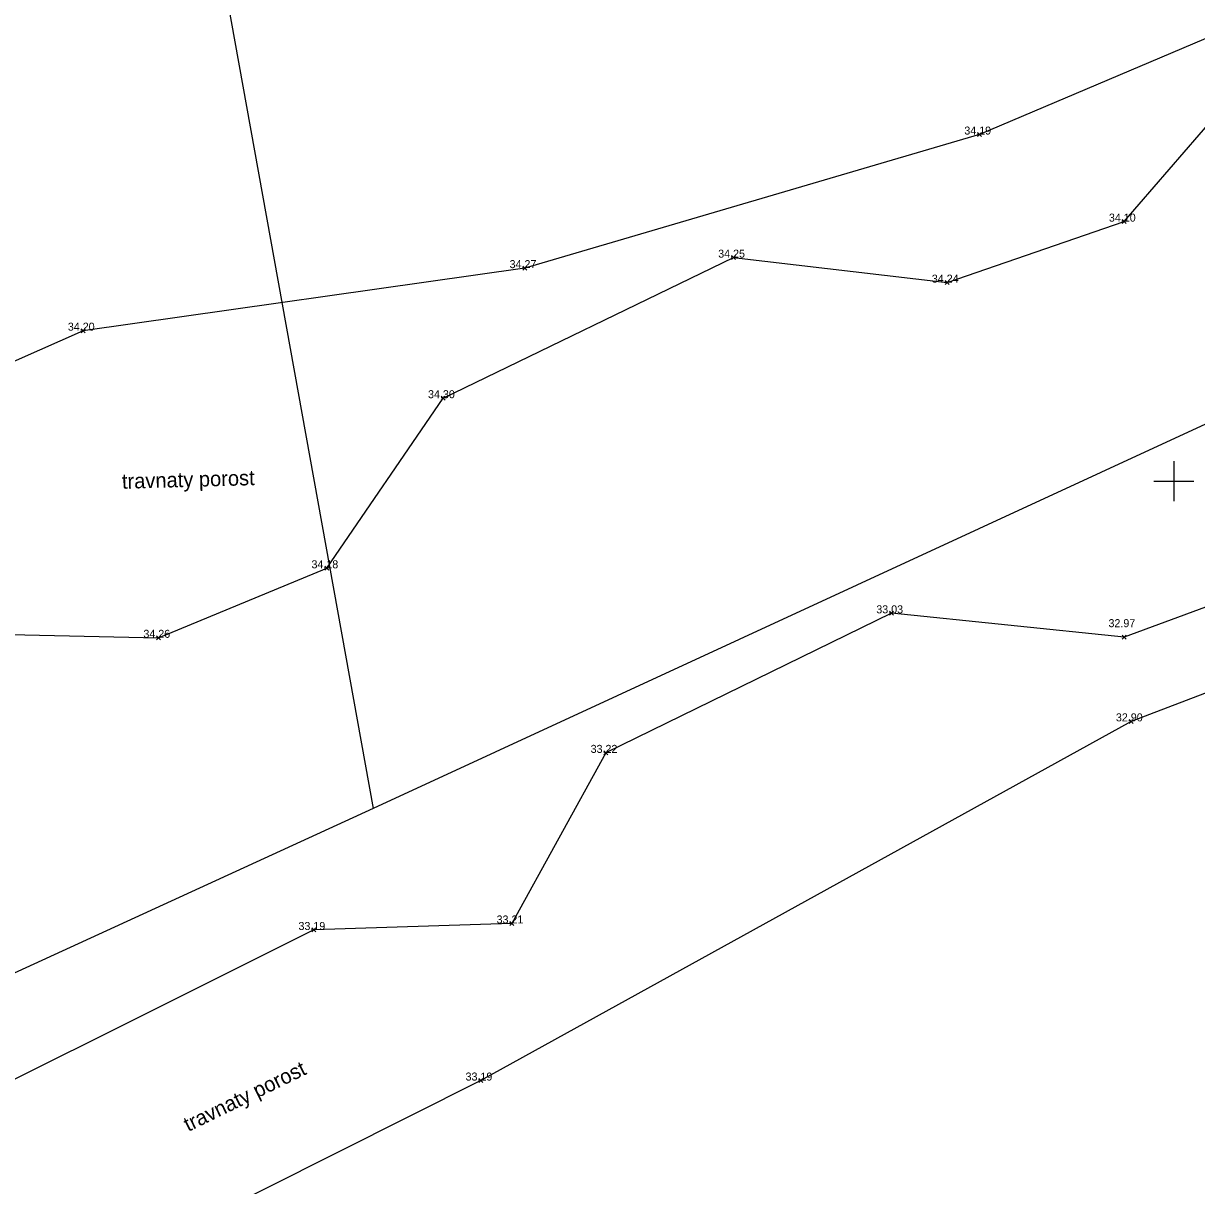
# Model space of a CAD drawing. Extents: x -772865 to -772533, y -1034366 to -1034132.
# Drawn here: x -772747.99 to -772724.54, y -1034264.08 to -1034240.85 of the extents above; entities that cross this region are included whole.
import ezdxf

# ---------------------------------------------------------------- set-up
doc = ezdxf.new("R2010")
doc.units = 0
for name, color, linetype in [('body', 7, 'Continuous'), ('KM_hranice', 7, 'Continuous'), ('mistni_popis', 7, 'Continuous'), ('oddeleni_ploch', 7, 'Continuous'), ('souradnicova_sit', 7, 'Continuous'), ('stromy_kere', 7, 'Continuous'), ('vyskove_koty', 7, 'Continuous')]:
    doc.layers.add(name, color=color, linetype=linetype)

msp = doc.modelspace()

# ---------------------------------------------------------------- linework, layer by layer
at = {"layer": 'body'}
for p, q in [((-772728.84, -1034243.11), (-772728.92, -1034243.03)), ((-772728.92, -1034243.11), (-772728.84, -1034243.03)), ((-772725.95, -1034244.85), (-772726.03, -1034244.77)), ((-772726.03, -1034244.85), (-772725.95, -1034244.77)), ((-772733.76, -1034245.57), (-772733.84, -1034245.49)), ((-772733.84, -1034245.57), (-772733.76, -1034245.49)), ((-772737.93, -1034245.78), (-772738.01, -1034245.7)), ((-772738.01, -1034245.78), (-772737.93, -1034245.7)), ((-772729.49, -1034246.07), (-772729.57, -1034245.99)), ((-772729.57, -1034246.07), (-772729.49, -1034245.99)), ((-772746.76, -1034247.03), (-772746.84, -1034246.95)), ((-772746.84, -1034247.03), (-772746.76, -1034246.95)), ((-772739.56, -1034248.38), (-772739.64, -1034248.3)), ((-772739.64, -1034248.38), (-772739.56, -1034248.3)), ((-772741.89, -1034251.78), (-772741.97, -1034251.7)), ((-772741.97, -1034251.78), (-772741.89, -1034251.7)), ((-772730.6, -1034252.68), (-772730.68, -1034252.6)), ((-772730.68, -1034252.68), (-772730.6, -1034252.6)), ((-772745.25, -1034253.17), (-772745.33, -1034253.09)), ((-772745.33, -1034253.17), (-772745.25, -1034253.09)), ((-772725.95, -1034253.16), (-772726.03, -1034253.08)), ((-772726.03, -1034253.16), (-772725.95, -1034253.08)), ((-772725.81, -1034254.84), (-772725.89, -1034254.76)), ((-772725.89, -1034254.84), (-772725.81, -1034254.76)), ((-772736.31, -1034255.47), (-772736.39, -1034255.39)), ((-772736.39, -1034255.47), (-772736.31, -1034255.39)), ((-772738.19, -1034258.88), (-772738.27, -1034258.8)), ((-772738.27, -1034258.88), (-772738.19, -1034258.8)), ((-772742.15, -1034259.01), (-772742.23, -1034258.93)), ((-772742.23, -1034259.01), (-772742.15, -1034258.93)), ((-772738.81, -1034262.02), (-772738.89, -1034261.94)), ((-772738.89, -1034262.02), (-772738.81, -1034261.94))]:
    msp.add_line(p, q, dxfattribs=at)
at = {"layer": 'KM_hranice'}
for p, q in [((-772747.65, -1034219.69), (-772741, -1034256.54)), ((-772692.32, -1034234.06), (-772741, -1034256.54)), ((-772741, -1034256.54), (-772755.58, -1034263.23))]:
    msp.add_line(p, q, dxfattribs=at)
at = {"layer": 'oddeleni_ploch'}
for points in [[(-772574.1, -1034196.14), (-772586.87, -1034201.34), (-772598.23, -1034205.06), (-772614.53, -1034207.42), (-772626.93, -1034206.95), (-772636.66, -1034207.26), (-772647.96, -1034208.36), (-772659.39, -1034213.08), (-772672.58, -1034218.62), (-772687.49, -1034225.14), (-772703.01, -1034232.02), (-772714.35, -1034236.9), (-772728.88, -1034243.07), (-772737.97, -1034245.74), (-772746.8, -1034246.99), (-772753.85, -1034250.11), (-772762.71, -1034257.3), (-772782.05, -1034269.18), (-772797.09, -1034276.39), (-772810.61, -1034282.39), (-772816.13, -1034284.08), (-772822.76, -1034283.4), (-772826.73, -1034280.27)], [(-772569.67, -1034207.72), (-772578.35, -1034211.18), (-772588.33, -1034216.15), (-772592.11, -1034217.46), (-772598.89, -1034219.1), (-772610.21, -1034219.57), (-772621.14, -1034219.48), (-772637.34, -1034221.06), (-772647.54, -1034222.08), (-772674.34, -1034233.24), (-772685.01, -1034239.21), (-772697.33, -1034242.95), (-772712.12, -1034249.56), (-772725.85, -1034254.8), (-772738.85, -1034261.98), (-772750.37, -1034267.76), (-772764, -1034272.65), (-772783.9, -1034280.59), (-772796.38, -1034286.28), (-772810.31, -1034291.67), (-772823.61, -1034294.35), (-772828.52, -1034296.12), (-772827.01, -1034302.81), (-772823.23, -1034300.75)]]:
    msp.add_lwpolyline(points, dxfattribs=at)
at = {"layer": 'souradnicova_sit'}
for p, q in [((-772725, -1034249.6), (-772725, -1034250.4)), ((-772725.4, -1034250), (-772724.6, -1034250))]:
    msp.add_line(p, q, dxfattribs=at)
at = {"layer": 'stromy_kere'}
for points in [[(-772765.65, -1034261.7), (-772757.35, -1034258.12), (-772757.45, -1034255.36), (-772753.97, -1034253.1), (-772751.37, -1034253.13), (-772749.46, -1034253.04), (-772745.29, -1034253.13), (-772741.93, -1034251.74), (-772739.6, -1034248.34), (-772733.8, -1034245.53), (-772729.53, -1034246.03), (-772725.99, -1034244.81), (-772724.19, -1034242.73), (-772713.9, -1034238.45), (-772703.51, -1034234.42), (-772694.98, -1034230.19)], [(-772697.8, -1034241.28), (-772703.73, -1034242.07), (-772708.05, -1034246.5), (-772725.99, -1034253.12), (-772730.64, -1034252.64), (-772736.35, -1034255.43), (-772738.23, -1034258.84), (-772742.19, -1034258.97), (-772751.86, -1034263.8), (-772757.95, -1034266.78), (-772758.48, -1034269.42), (-772764.72, -1034271.25), (-772777.99, -1034275.49), (-772780.54, -1034274.19), (-772782.8, -1034275.98), (-772782.89, -1034278.68), (-772790.87, -1034282.58), (-772810.31, -1034291.67)]]:
    msp.add_lwpolyline(points, dxfattribs=at)

# ---------------------------------------------------------------- texts
at = {"layer": 'mistni_popis'}
for rotation, p in [(1.6043, (-772746.02, -1034250.151)), (26.0123, (-772744.698, -1034263.009))]:
    msp.add_text('travnaty porost', height=0.3, rotation=rotation, dxfattribs=at).set_placement(p)
at = {"layer": 'vyskove_koty'}
for s, p in [('34.19', (-772729.185, -1034243.07)), ('34.10', (-772726.295, -1034244.81)), ('34.25', (-772734.105, -1034245.53)), ('34.27', (-772738.275, -1034245.74)), ('34.24', (-772729.835, -1034246.03)), ('34.20', (-772747.105, -1034246.99)), ('34.30', (-772739.905, -1034248.34)), ('34.18', (-772742.235, -1034251.74)), ('33.03', (-772730.945, -1034252.64)), ('32.97', (-772726.304, -1034252.917)), ('34.26', (-772745.595, -1034253.13)), ('32.90', (-772726.155, -1034254.8)), ('33.22', (-772736.655, -1034255.43)), ('33.19', (-772742.495, -1034258.97)), ('33.21', (-772738.535, -1034258.84)), ('33.19', (-772739.155, -1034261.98))]:
    msp.add_text(s, height=0.16, dxfattribs=at).set_placement(p)

doc.saveas('drawing.dxf')
